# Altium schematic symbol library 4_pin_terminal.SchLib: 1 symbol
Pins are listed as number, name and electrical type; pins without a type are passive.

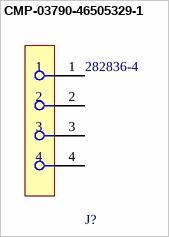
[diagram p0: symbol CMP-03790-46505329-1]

## CMP-03790-46505329-1
designator J?, comment 282836-4
282836-4 Connector, Terminal Block; Wire Receptacle; 4 Pos.; 16-30 AWG; 0.197 in. CL; Sid; NexarPartId: 46505329; Manufacturer Lifecycle Status: ACTIVE; Number of Contacts: 4; Max Supply Voltage (AC): 300V; Wire Gauge (Min): 30AWG; Max Current Rating: 13.5A; Approvals: UL; Number of Levels: 1; Thread Size: M3; Connector System: Wire-to-Board; Voltage Rating (DC): 250V; Pitch: 5mm; Plating: Brass; Tail Length: 3.5mm
footprint FP-282836-4-MFG
pins: 1, 2, 3, 4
